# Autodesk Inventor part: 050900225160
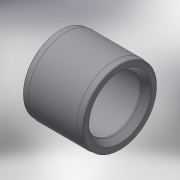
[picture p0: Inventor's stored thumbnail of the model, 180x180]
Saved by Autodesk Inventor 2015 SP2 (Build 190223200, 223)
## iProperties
Created: 2017-11
Part Number: 050900225160
Material: Generic
Description: PLASSON BUSHING-CEMENT PVC 225-160
Document SubType Name: Modeling
Designer: KIM
Density: 1 g/cm^3
Appearance: Default
Author: KIM
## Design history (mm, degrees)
derived "050900.ipt"
feature "Solid1::050900.ipt"
tag "TaggingFeature1"
body "Solid1"
other parameters: "d1" = 225, "d2" = 86, "d3" = 119, "d7" = 11.9, "d11" = 11.9, "d12" = 2.25, "d14" = 2.25, "d15" = 11.9, "d17" = 2.25, "d18" = 2.25, "d19" = 142.4, "d20" = 6.6, "d21" = 24.78, "D_" = 225, "L_" = 119, "l_" = 86, "z_" = 2
